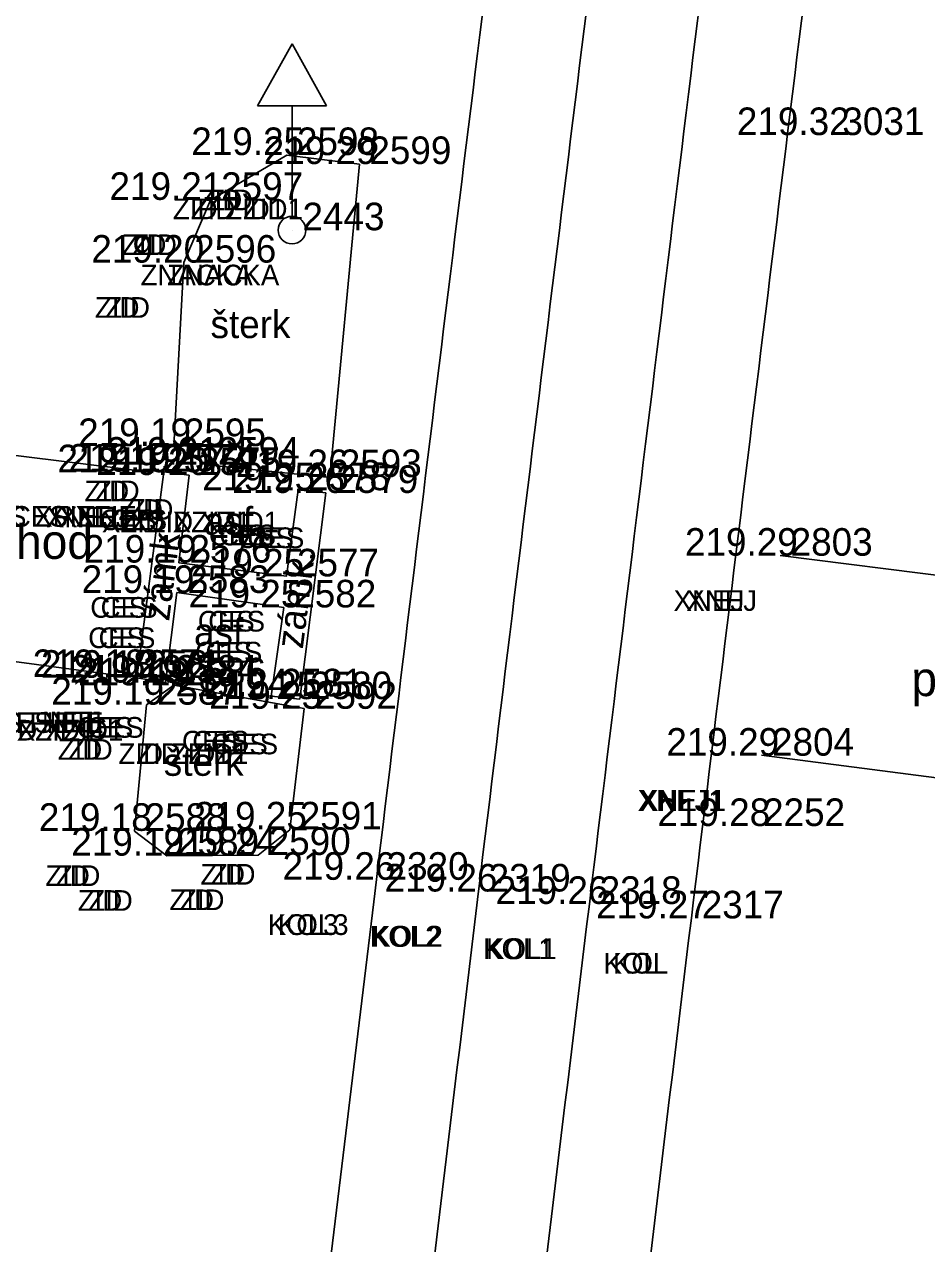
# Model space of a CAD drawing. Extents: x -471047 to -470889, y -1102859 to -1102000.
# Drawn here: x -470941.29 to -470928.21, y -1102212.58 to -1102194.89 of the extents above; entities that cross this region are included whole.
import ezdxf

# ---------------------------------------------------------------- set-up
doc = ezdxf.new("R2010")
doc.units = 0
for name, color, linetype in [('Vrstva 1', 7, 'Continuous'), ('Vrstva 19', 7, 'Continuous'), ('Vrstva 21', 7, 'Continuous'), ('Vrstva 22', 7, 'Continuous'), ('Vrstva 34', 7, 'Continuous'), ('Vrstva 35', 7, 'Continuous'), ('Vrstva 36', 7, 'Continuous'), ('Vrstva 38', 7, 'Continuous'), ('Vrstva 8', 7, 'Continuous')]:
    doc.layers.add(name, color=color, linetype=linetype)

msp = doc.modelspace()

# ---------------------------------------------------------------- linework, layer by layer
at = {"layer": 'Vrstva 1'}
for points in [[(-471040.344, -1102858.385), (-471031.676, -1102846.187), (-471026.357, -1102838.629), (-471023.212, -1102833.975), (-471019.21, -1102827.465), (-471016.861, -1102823.272), (-471013.099, -1102815.912), (-471010.824, -1102810.955), (-471007.329, -1102802.292), (-471005.34, -1102796.515), (-471002.842, -1102787.838), (-471001.3, -1102780.997), (-471000.19, -1102774.713), (-470999.247, -1102768.204), (-470998.794, -1102764.784), (-470997.199, -1102751.812), (-470994.899, -1102732.807), (-470992.551, -1102713.262), (-470990.326, -1102694.887), (-470988.122, -1102676.57), (-470985.812, -1102657.305), (-470983.537, -1102638.407), (-470981.386, -1102620.622), (-470979.843, -1102608.014), (-470976.377, -1102579.253), (-470972.945, -1102550.69), (-470970.475, -1102530.206), (-470967.905, -1102508.801), (-470965.053, -1102485.131), (-470962.734, -1102465.9), (-470960.173, -1102444.812), (-470957.795, -1102425.103), (-470954.965, -1102401.839), (-470953.834, -1102392.574), (-470952.33, -1102379.985), (-470950.744, -1102366.853), (-470948.978, -1102352.106), (-470947.037, -1102335.844), (-470944.949, -1102318.462), (-470944.013, -1102310.745), (-470942.39, -1102297.267), (-470939.519, -1102273.45), (-470937.593, -1102257.43), (-470936.064, -1102244.81), (-470934.114, -1102228.634), (-470931.621, -1102207.856), (-470929.536, -1102190.857), (-470926.572, -1102166.31), (-470924.91, -1102152.663), (-470923.413, -1102140.333), (-470921.923, -1102127.669), (-470921.155, -1102120.084), (-470920.446, -1102109.574), (-470919.912, -1102099.137), (-470919.63, -1102088.981), (-470919.523, -1102081.193), (-470919.563, -1102070.395), (-470919.714, -1102064.236), (-470920.134, -1102054.704), (-470920.462, -1102047.615), (-470920.599, -1102044.52), (-470920.743, -1102041.873), (-470921.125, -1102034.455), (-470921.774, -1102030.337), (-470922.418, -1102027.787), (-470923.734, -1102023.93), (-470924.872, -1102021.434), (-470926.752, -1102018.182), (-470927.953, -1102016.45), (-470929.616, -1102014.424), (-470932.252, -1102011.756), (-470935.111, -1102009.425), (-470938.391, -1102007.371), (-470942.651, -1102005.401)], [(-471041.328, -1102857.18), (-471032.144, -1102844.242), (-471027.583, -1102837.763), (-471024.388, -1102833.028), (-471020.451, -1102826.6), (-471018.089, -1102822.378), (-471014.542, -1102815.445), (-471012.233, -1102810.418), (-471009.247, -1102803.108), (-471006.795, -1102796.098), (-471004.315, -1102787.532), (-471002.782, -1102780.723), (-471001.674, -1102774.458), (-471000.75, -1102768.095), (-471000.28, -1102764.601), (-470998.692, -1102751.741), (-470996.378, -1102732.635), (-470994.028, -1102713.058), (-470991.808, -1102694.749), (-470989.616, -1102676.447), (-470987.284, -1102657.013), (-470985.031, -1102638.272), (-470982.87, -1102620.431), (-470981.334, -1102607.933), (-470977.881, -1102579.263), (-470974.429, -1102550.492), (-470971.964, -1102530.054), (-470969.391, -1102508.607), (-470966.54, -1102484.984), (-470964.231, -1102465.853), (-470961.679, -1102444.752), (-470959.304, -1102425.078), (-470956.455, -1102401.634), (-470955.339, -1102392.489), (-470953.812, -1102379.71), (-470952.249, -1102366.808), (-470950.479, -1102352.023), (-470948.536, -1102335.868), (-470946.426, -1102318.233), (-470945.493, -1102310.531), (-470943.864, -1102297.013), (-470940.984, -1102273.071), (-470939.078, -1102257.195), (-470937.559, -1102244.684), (-470935.592, -1102228.353), (-470933.101, -1102207.653), (-470931.011, -1102190.57), (-470928.046, -1102166.021), (-470926.409, -1102152.578), (-470924.898, -1102140.121), (-470923.427, -1102127.544), (-470922.647, -1102119.826), (-470921.919, -1102109.229), (-470921.42, -1102099.134), (-470921.127, -1102089.016), (-470921.023, -1102081.453), (-470921.061, -1102070.468), (-470921.209, -1102064.314), (-470921.666, -1102053.966), (-470922.156, -1102043.345), (-470922.299, -1102039.934), (-470922.637, -1102034.36), (-470923.091, -1102031.241), (-470923.847, -1102028.247), (-470925.083, -1102024.594), (-470926.222, -1102022.086), (-470928.04, -1102018.943), (-470929.138, -1102017.357), (-470930.929, -1102015.175), (-470933.062, -1102013.049), (-470936.379, -1102010.368), (-470939.169, -1102008.662), (-470942.899, -1102006.906), (-470945.661, -1102005.908)], [(-471043.557, -1102855.955), (-471035.129, -1102844.026), (-471029.872, -1102836.499), (-471026.577, -1102831.578), (-471022.675, -1102825.415), (-471020.123, -1102821.053), (-471016.667, -1102814.59), (-471014.208, -1102809.45), (-471011.177, -1102802.451), (-471008.55, -1102795.333), (-471006.082, -1102787.209), (-471004.464, -1102780.376), (-471003.265, -1102774.167), (-471002.327, -1102767.948), (-471001.636, -1102762.527), (-471000.297, -1102751.605), (-470997.959, -1102732.524), (-470995.602, -1102712.802), (-470993.412, -1102694.623), (-470991.21, -1102676.17), (-470988.891, -1102656.857), (-470986.625, -1102638.083), (-470984.455, -1102620.195), (-470982.936, -1102607.733), (-470979.497, -1102579.223), (-470976.023, -1102550.279), (-470973.554, -1102529.822), (-470970.991, -1102508.497), (-470968.146, -1102484.787), (-470965.835, -1102465.72), (-470963.284, -1102444.529), (-470960.91, -1102424.942), (-470958.043, -1102401.343), (-470956.946, -1102392.356), (-470955.396, -1102379.408), (-470953.851, -1102366.636), (-470952.049, -1102351.733), (-470950.124, -1102335.611), (-470948.034, -1102318.083), (-470947.094, -1102310.328), (-470945.421, -1102296.51), (-470942.58, -1102272.848), (-470940.675, -1102256.948), (-470939.176, -1102244.526), (-470937.187, -1102228.174), (-470934.708, -1102207.467), (-470932.621, -1102190.433), (-470929.634, -1102165.778), (-470928.004, -1102152.415), (-470926.45, -1102139.595), (-470925.003, -1102127.418), (-470924.249, -1102119.695), (-470923.515, -1102109.093), (-470923.018, -1102099.069), (-470922.711, -1102088.911), (-470922.643, -1102081.356), (-470922.797, -1102070.414), (-470923.018, -1102064.454), (-470923.52, -1102053.203), (-470923.823, -1102047.529), (-470924.123, -1102041.506), (-470924.462, -1102037.486), (-470924.934, -1102031.904), (-470925.664, -1102028.672), (-470926.771, -1102025.506), (-470927.959, -1102022.914), (-470929.674, -1102020.028), (-470930.76, -1102018.498), (-470932.447, -1102016.478), (-470935.215, -1102013.816), (-470937.644, -1102011.98), (-470940.381, -1102010.371), (-470943.968, -1102008.669), (-470947.145, -1102007.524), (-470950.874, -1102006.74)], [(-471044.756, -1102855.056), (-471036.376, -1102843.177), (-471031.167, -1102835.741), (-471027.859, -1102830.8), (-471023.934, -1102824.593), (-471021.43, -1102820.312), (-471018.011, -1102813.91), (-471015.536, -1102808.75), (-471012.578, -1102801.897), (-471009.95, -1102794.77), (-471007.561, -1102786.914), (-471005.936, -1102780.074), (-471004.727, -1102773.818), (-471003.828, -1102767.827), (-471003.121, -1102762.345), (-471001.787, -1102751.467), (-470999.446, -1102732.348), (-470997.073, -1102712.539), (-470994.902, -1102694.521), (-470992.696, -1102676.023), (-470990.376, -1102656.68), (-470988.131, -1102638.071), (-470985.947, -1102620.018), (-470984.417, -1102607.512), (-470980.993, -1102579.08), (-470977.514, -1102550.137), (-470975.048, -1102529.649), (-470972.488, -1102508.37), (-470969.618, -1102484.508), (-470967.34, -1102465.669), (-470964.767, -1102444.39), (-470962.402, -1102424.781), (-470959.534, -1102401.193), (-470958.432, -1102392.151), (-470956.883, -1102379.208), (-470955.335, -1102366.424), (-470953.535, -1102351.506), (-470951.606, -1102335.399), (-470949.519, -1102317.94), (-470948.575, -1102310.159), (-470946.889, -1102296.144), (-470944.056, -1102272.618), (-470942.139, -1102256.659), (-470940.657, -1102244.341), (-470938.638, -1102227.749), (-470936.19, -1102207.298), (-470934.102, -1102190.255), (-470931.124, -1102165.639), (-470929.492, -1102152.254), (-470927.915, -1102139.252), (-470926.46, -1102127.103), (-470925.74, -1102119.604), (-470925.012, -1102108.913), (-470924.523, -1102099.054), (-470924.217, -1102088.866), (-470924.148, -1102081.334), (-470924.301, -1102070.391), (-470924.518, -1102064.43), (-470924.97, -1102054.435), (-470925.588, -1102041.569), (-470925.963, -1102035.313), (-470926.405, -1102032.225), (-470927.078, -1102029.198), (-470928.123, -1102026.148), (-470929.318, -1102023.558), (-470930.84, -1102020.97), (-470931.868, -1102019.515), (-470933.443, -1102017.605), (-470936.26, -1102014.885), (-470938.429, -1102013.255), (-470941.213, -1102011.639), (-470944.847, -1102009.927), (-470947.723, -1102008.912), (-470951.444, -1102008.161), (-470954.511, -1102007.931), (-470957.895, -1102008.041)]]:
    msp.add_spline(points, degree=3, dxfattribs=at)
at = {"layer": 'Vrstva 19'}
for p, q in [((-470937.413, -1102195.178), (-470937.913, -1102196.078)), ((-470937.413, -1102195.178), (-470936.913, -1102196.078)), ((-470936.913, -1102196.078), (-470937.913, -1102196.078)), ((-470937.413, -1102196.078), (-470937.413, -1102197.678))]:
    msp.add_line(p, q, dxfattribs=at)
msp.add_circle((-470937.413, -1102197.878), 0.2, dxfattribs=at)
at = {"layer": 'Vrstva 21'}
for p, q in [((-470938.593, -1102197.443), (-470937.487, -1102196.791)), ((-470937.487, -1102196.791), (-470936.435, -1102196.922)), ((-470936.866, -1102201.464), (-470936.435, -1102196.922)), ((-470938.983, -1102198.347), (-470938.593, -1102197.443)), ((-470939.126, -1102201.006), (-470938.983, -1102198.347)), ((-470938.642, -1102201.284), (-470939.126, -1102201.006)), ((-470936.866, -1102201.464), (-470938.642, -1102201.284)), ((-470939.129, -1102204.476), (-470939.524, -1102204.761)), ((-470939.129, -1102204.476), (-470937.235, -1102204.818)), ((-470939.524, -1102204.761), (-470939.697, -1102206.593)), ((-470937.447, -1102206.574), (-470937.235, -1102204.818)), ((-470939.697, -1102206.593), (-470939.23, -1102206.953)), ((-470937.902, -1102206.941), (-470937.447, -1102206.574)), ((-470939.23, -1102206.953), (-470937.902, -1102206.941))]:
    msp.add_line(p, q, dxfattribs=at)
at = {"layer": 'Vrstva 34'}
for p, q in [((-470929.58, -1102196.5), (-470929.58, -1102196.5)), ((-470937.49, -1102196.79), (-470937.49, -1102196.79)), ((-470936.44, -1102196.92), (-470936.44, -1102196.92)), ((-470938.59, -1102197.44), (-470938.59, -1102197.44)), ((-470937.41, -1102197.88), (-470937.41, -1102197.88)), ((-470938.98, -1102198.35), (-470938.98, -1102198.35)), ((-470939.13, -1102201.01), (-470939.13, -1102201.01)), ((-470939.43, -1102201.39), (-470939.43, -1102201.39)), ((-470939.27, -1102201.38), (-470939.27, -1102201.38)), ((-470938.91, -1102201.43), (-470938.91, -1102201.43)), ((-470938.64, -1102201.28), (-470938.64, -1102201.28)), ((-470936.87, -1102201.46), (-470936.87, -1102201.46)), ((-470937.33, -1102201.65), (-470937.33, -1102201.65)), ((-470936.92, -1102201.69), (-470936.92, -1102201.69)), ((-470930.33, -1102202.6), (-470930.33, -1102202.6)), ((-470939.05, -1102202.7), (-470939.05, -1102202.7)), ((-470937.49, -1102202.9), (-470937.49, -1102202.9)), ((-470939.08, -1102203.14), (-470939.08, -1102203.14)), ((-470937.53, -1102203.35), (-470937.53, -1102203.35)), ((-470939.79, -1102204.36), (-470939.79, -1102204.36)), ((-470939.67, -1102204.37), (-470939.67, -1102204.37)), ((-470939.25, -1102204.44), (-470939.25, -1102204.44)), ((-470939.13, -1102204.48), (-470939.13, -1102204.48)), ((-470939.52, -1102204.76), (-470939.52, -1102204.76)), ((-470937.72, -1102204.64), (-470937.72, -1102204.64)), ((-470937.3, -1102204.68), (-470937.3, -1102204.68)), ((-470937.23, -1102204.82), (-470937.23, -1102204.82)), ((-470930.6, -1102205.5), (-470930.6, -1102205.5)), ((-470930.73, -1102206.52), (-470930.73, -1102206.52)), ((-470939.7, -1102206.59), (-470939.7, -1102206.59)), ((-470937.45, -1102206.57), (-470937.45, -1102206.57)), ((-470939.23, -1102206.95), (-470939.23, -1102206.95)), ((-470937.9, -1102206.94), (-470937.9, -1102206.94)), ((-470936.19, -1102207.3), (-470936.19, -1102207.3)), ((-470934.71, -1102207.47), (-470934.71, -1102207.47)), ((-470933.1, -1102207.65), (-470933.1, -1102207.65)), ((-470931.62, -1102207.86), (-470931.62, -1102207.86))]:
    msp.add_line(p, q, dxfattribs=at)
at = {"layer": 'Vrstva 8'}
for p, q in [((-470939.428, -1102201.394), (-470942.822, -1102200.97)), ((-470939.272, -1102201.383), (-470939.666, -1102204.37)), ((-470939.272, -1102201.383), (-470938.905, -1102201.432)), ((-470938.905, -1102201.432), (-470939.054, -1102202.701)), ((-470937.491, -1102202.899), (-470937.326, -1102201.646)), ((-470937.326, -1102201.646), (-470936.922, -1102201.687)), ((-470936.922, -1102201.687), (-470937.298, -1102204.682)), ((-470930.332, -1102202.597), (-470922.724, -1102203.56)), ((-470939.054, -1102202.701), (-470937.491, -1102202.899)), ((-470939.083, -1102203.136), (-470939.247, -1102204.441)), ((-470937.534, -1102203.353), (-470939.083, -1102203.136)), ((-470937.717, -1102204.638), (-470937.534, -1102203.353)), ((-470943.243, -1102203.894), (-470939.789, -1102204.358)), ((-470939.247, -1102204.441), (-470939.666, -1102204.37)), ((-470937.298, -1102204.682), (-470937.717, -1102204.638)), ((-470930.605, -1102205.495), (-470923.171, -1102206.453))]:
    msp.add_line(p, q, dxfattribs=at)

# ---------------------------------------------------------------- texts
at = {"layer": 'Vrstva 22'}
for s, height, p in [('šterk', 0.4, (-470938.595, -1102199.444)), ('asf.', 0.4, (-470938.69, -1102202.296)), ('přechod', 0.5, (-470942.716, -1102202.646)), ('asf.', 0.4, (-470938.835, -1102203.907)), ('přechod', 0.5, (-470928.43, -1102204.636)), ('šterk', 0.4, (-470939.273, -1102205.792))]:
    msp.add_text(s, height=height, dxfattribs=at).set_placement(p)
for p in [(-470939.196, -1102203.558), (-470937.257, -1102203.961)]:
    msp.add_text('zámk.', height=0.4, rotation=82.8361, dxfattribs=at).set_placement(p)
at = {"layer": 'Vrstva 35'}
for s, p in [('ZID', (-470938.781, -1102197.59)), ('ZID', (-470938.629, -1102197.59)), ('ZID ZID1', (-470939.14, -1102197.72)), ('ZID ZID1', (-470938.882, -1102197.72)), ('ZID', (-470939.881, -1102198.24)), ('ZID', (-470939.729, -1102198.24)), ('ZNACKA', (-470939.61, -1102198.68)), ('ZNACKA', (-470939.224, -1102198.68)), ('ZID', (-470940.271, -1102199.15)), ('ZID', (-470940.119, -1102199.15)), ('ZID', (-470940.421, -1102201.81)), ('ZID', (-470940.269, -1102201.81)), ('ZID', (-470939.931, -1102202.08)), ('ZID', (-470939.779, -1102202.08)), ('XCES XFIE', (-470942.357, -1102202.18)), ('XCES XFIE', (-470941.759, -1102202.18)), ('XNEJ', (-470940.98, -1102202.19)), ('XNEJ', (-470940.794, -1102202.19)), ('CES', (-470940.199, -1102202.23)), ('XZID XZID1', (-470940.17, -1102202.26)), ('CES', (-470940.049, -1102202.23)), ('XZID XZID1', (-470939.762, -1102202.26)), ('CES', (-470938.619, -1102202.45)), ('CES', (-470938.469, -1102202.45)), ('CES', (-470938.209, -1102202.49)), ('CES', (-470938.059, -1102202.49)), ('CES', (-470940.339, -1102203.5)), ('CES', (-470940.189, -1102203.5)), ('XNEJ', (-470931.88, -1102203.4)), ('XNEJ', (-470931.694, -1102203.4)), ('CES', (-470938.779, -1102203.7)), ('CES', (-470938.629, -1102203.7)), ('CES', (-470940.369, -1102203.94)), ('CES', (-470940.219, -1102203.94)), ('CES', (-470938.819, -1102204.15)), ('CES', (-470938.669, -1102204.15)), ('CES FIE', (-470942.158, -1102205.17)), ('CES FIE', (-470941.709, -1102205.17)), ('NEJ', (-470941.04, -1102205.16)), ('NEJ', (-470940.929, -1102205.16)), ('CES', (-470940.539, -1102205.24)), ('CES', (-470940.389, -1102205.24)), ('XZID XZID1', (-470942.43, -1102205.28)), ('XZID XZID1', (-470942.022, -1102205.28)), ('CES', (-470939.009, -1102205.44)), ('CES', (-470938.859, -1102205.44)), ('ZID', (-470940.811, -1102205.56)), ('ZID', (-470940.659, -1102205.56)), ('ZID ZID1', (-470939.93, -1102205.62)), ('ZID ZID1', (-470939.672, -1102205.62)), ('CES', (-470938.589, -1102205.48)), ('CES', (-470938.439, -1102205.48)), ('XNEJ1', (-470932.4, -1102206.3)), ('XNEJ1', (-470932.367, -1102206.3)), ('ZID', (-470940.991, -1102207.39)), ('ZID', (-470940.839, -1102207.39)), ('ZID', (-470938.741, -1102207.37)), ('ZID', (-470938.589, -1102207.37)), ('ZID', (-470939.191, -1102207.74)), ('ZID', (-470939.039, -1102207.74)), ('ZID', (-470940.521, -1102207.75)), ('ZID', (-470940.369, -1102207.75)), ('KOL3', (-470937.765, -1102208.1)), ('KOL3', (-470937.618, -1102208.1)), ('KOL2', (-470936.285, -1102208.27)), ('KOL2', (-470936.251, -1102208.27)), ('KOL1', (-470934.642, -1102208.45)), ('KOL1', (-470934.6, -1102208.45)), ('KOL', (-470932.895, -1102208.66)), ('KOL', (-470932.759, -1102208.66))]:
    msp.add_text(s, height=0.3, dxfattribs=at).set_placement(p)
at = {"layer": 'Vrstva 36'}
for s, p in [(' 3031', (-470929.58, -1102196.5)), (' 2598', (-470937.49, -1102196.79)), (' 2599', (-470936.44, -1102196.92)), (' 2597', (-470938.59, -1102197.44)), (' 2443', (-470937.41, -1102197.88)), (' 2596', (-470938.98, -1102198.35)), (' 2595', (-470939.13, -1102201.01)), (' 2594', (-470938.64, -1102201.28)), (' 2572', (-470939.43, -1102201.39)), (' 2574', (-470939.27, -1102201.38)), (' 2575', (-470938.91, -1102201.43)), (' 2593', (-470936.87, -1102201.46)), (' 2578', (-470937.33, -1102201.65)), (' 2579', (-470936.92, -1102201.69)), (' 2576', (-470939.05, -1102202.7)), (' 2803', (-470930.33, -1102202.6)), (' 2577', (-470937.49, -1102202.9)), (' 2583', (-470939.08, -1102203.14)), (' 2582', (-470937.53, -1102203.35)), (' 2571', (-470939.79, -1102204.36)), (' 2585', (-470939.67, -1102204.37)), (' 2584', (-470939.25, -1102204.44)), (' 2586', (-470939.13, -1102204.48)), (' 2581', (-470937.72, -1102204.64)), (' 2587', (-470939.52, -1102204.76)), (' 2580', (-470937.3, -1102204.68)), (' 2592', (-470937.23, -1102204.82)), (' 2804', (-470930.6, -1102205.5)), (' 2588', (-470939.7, -1102206.59)), (' 2591', (-470937.45, -1102206.57)), (' 2252', (-470930.73, -1102206.52)), (' 2589', (-470939.23, -1102206.95)), (' 2590', (-470937.9, -1102206.94)), (' 2320', (-470936.19, -1102207.3)), (' 2319', (-470934.71, -1102207.47)), (' 2318', (-470933.1, -1102207.65)), (' 2317', (-470931.62, -1102207.86))]:
    msp.add_text(s, height=0.4, dxfattribs=at).set_placement(p)
at = {"layer": 'Vrstva 38'}
for s, p in [('219.32 ', (-470930.961, -1102196.5)), ('219.25 ', (-470938.874, -1102196.79)), ('219.29 ', (-470937.824, -1102196.92)), ('219.21 ', (-470940.06, -1102197.44)), ('219.20 ', (-470940.323, -1102198.35)), ('219.19 ', (-470940.514, -1102201.01)), ('219.21 ', (-470940.11, -1102201.28)), ('219.19 ', (-470940.814, -1102201.39)), ('219.19 ', (-470940.654, -1102201.38)), ('219.20 ', (-470940.253, -1102201.43)), ('219.26 ', (-470938.23, -1102201.46)), ('219.25 ', (-470938.714, -1102201.65)), ('219.26 ', (-470938.28, -1102201.69)), ('219.19 ', (-470940.434, -1102202.7)), ('219.29 ', (-470931.714, -1102202.6)), ('219.25 ', (-470938.874, -1102202.9)), ('219.19 ', (-470940.464, -1102203.14)), ('219.25 ', (-470938.914, -1102203.35)), ('219.18 ', (-470941.174, -1102204.36)), ('219.18 ', (-470941.054, -1102204.37)), ('219.19 ', (-470940.634, -1102204.44)), ('219.19 ', (-470940.514, -1102204.48)), ('219.24 ', (-470939.102, -1102204.64)), ('219.19 ', (-470940.904, -1102204.76)), ('219.25 ', (-470938.684, -1102204.68)), ('219.25 ', (-470938.614, -1102204.82)), ('219.29 ', (-470931.984, -1102205.5)), ('219.18 ', (-470941.084, -1102206.59)), ('219.25 ', (-470938.834, -1102206.57)), ('219.28 ', (-470932.114, -1102206.52)), ('219.19 ', (-470940.614, -1102206.95)), ('219.24 ', (-470939.282, -1102206.94)), ('219.26 ', (-470937.55, -1102207.3)), ('219.26 ', (-470936.07, -1102207.47)), ('219.26 ', (-470934.46, -1102207.65)), ('219.27 ', (-470933.003, -1102207.86))]:
    msp.add_text(s, height=0.4, dxfattribs=at).set_placement(p)

doc.saveas('drawing.dxf')
